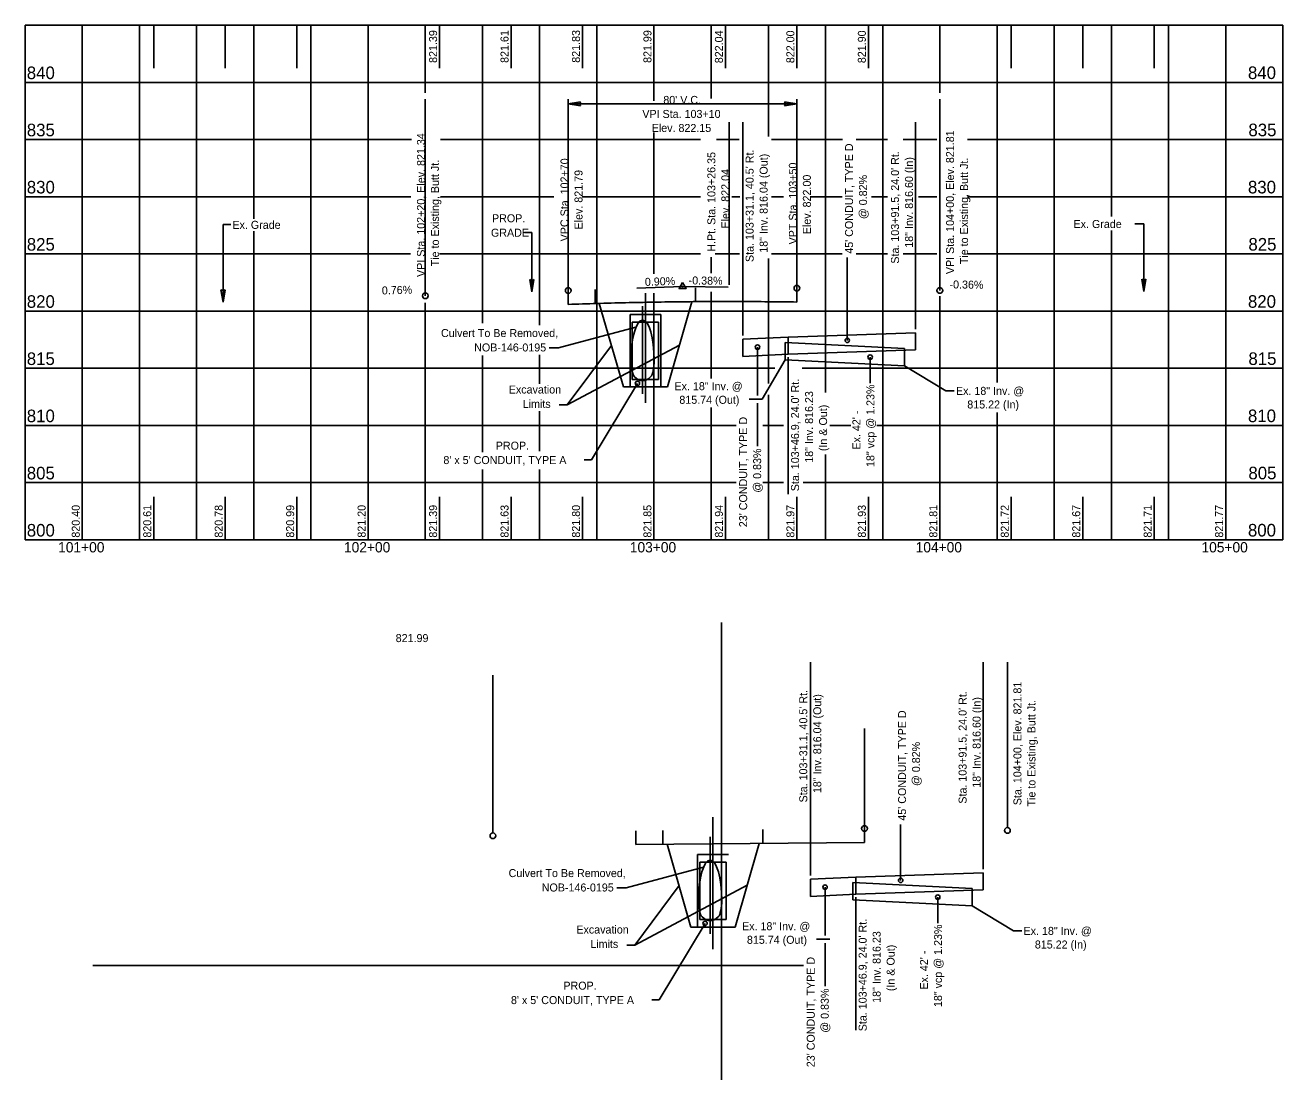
# Model space of a CAD drawing. Extents: x 1055 to 1496, y 611 to 1175.
# Drawn here: x 1055 to 1495, y 611.1 to 980 of the extents above; entities that cross this region are included whole.
import ezdxf

# ---------------------------------------------------------------- set-up
doc = ezdxf.new("R2010")
doc.units = 0
for name, color, linetype in [('BR_P_Gen_Joint_Filler', 7, 'Continuous'), ('Default', 7, 'Continuous'), ('DR_P_Culvert', 7, 'Continuous'), ('DR_X_Culvert', 7, 'Continuous'), ('PF_P_Grade_Line', 7, 'Continuous'), ('PF_P_Text', 7, 'Continuous'), ('PF_P_Text_Strip_Grades_20', 7, 'Continuous'), ('PF_X_Text', 7, 'Continuous'), ('SH_Major_Grid_Line', 7, 'Continuous')]:
    doc.layers.add(name, color=color, linetype=linetype)

msp = doc.modelspace()

# ---------------------------------------------------------------- linework, layer by layer
at = {"layer": 'BR_P_Gen_Joint_Filler'}
for p, q in [((1245, 952.47), (1249.33, 953.19)), ((1249.31, 951.75), (1245, 952.47)), ((1249.31, 951.75), (1249.31, 951.75)), ((1249.33, 953.19), (1249.33, 953.19)), ((1325, 952.47), (1320.67, 951.75)), ((1320.67, 951.75), (1320.67, 951.75)), ((1320.69, 953.19), (1320.69, 953.19)), ((1320.69, 953.19), (1325, 952.47)), ((1232.25, 886.7), (1231.52, 891.03)), ((1231.52, 891.03), (1231.52, 891.03)), ((1232.97, 891.01), (1232.25, 886.7)), ((1232.97, 891.01), (1232.97, 891.01)), ((1446.4, 886.8), (1445.68, 891.13)), ((1445.68, 891.13), (1445.68, 891.13)), ((1447.12, 891.12), (1446.4, 886.8)), ((1447.12, 891.12), (1447.12, 891.12)), ((1124.23, 883.1), (1123.51, 887.43)), ((1123.51, 887.43), (1123.51, 887.43)), ((1124.95, 887.42), (1124.23, 883.1)), ((1124.95, 887.42), (1124.95, 887.42))]:
    msp.add_line(p, q, dxfattribs=at)
for centre, start, end in [((1250.42, 952.46), 146.178, 212.8588), ((1319.58, 952.48), 326.178, 32.8588), ((1232.26, 892.12), 236.178, 302.8588), ((1446.41, 892.22), 236.178, 302.8588), ((1124.24, 888.52), 236.178, 302.8588)]:
    msp.add_arc(centre, 1.31, start, end, dxfattribs=at)
at = {"layer": 'DR_P_Culvert'}
for p, q in [((1272, 847.95), (1272, 886.27)), ((1266.61, 878.79), (1277.38, 878.79)), ((1266.61, 853.45), (1266.61, 878.79)), ((1267.38, 876.12), (1276.62, 876.12)), ((1267.38, 856.12), (1267.38, 876.12)), ((1276.62, 856.12), (1276.62, 876.12)), ((1277.38, 853.45), (1277.38, 878.79)), ((1321.94, 870.92), (1366.47, 872.4)), ((1366.47, 866.4), (1366.47, 872.4)), ((1306.13, 870.16), (1321.94, 870.92)), ((1306.13, 864.16), (1306.13, 870.16)), ((1321.94, 864.92), (1321.94, 870.92)), ((1306.13, 864.16), (1321.94, 864.92)), ((1321.94, 864.92), (1366.47, 866.4)), ((1267.38, 856.12), (1276.62, 856.12)), ((1266.61, 853.45), (1277.38, 853.45)), ((1295.64, 656.83), (1295.64, 702.97)), ((1290.25, 689.91), (1301.03, 689.91)), ((1290.25, 664.58), (1290.25, 689.91)), ((1291.03, 687.25), (1300.26, 687.25)), ((1291.03, 667.25), (1291.03, 687.25)), ((1300.26, 667.25), (1300.26, 687.25)), ((1329.78, 681.29), (1345.59, 682.05)), ((1345.59, 682.05), (1390.12, 683.53)), ((1345.59, 676.05), (1345.59, 682.05)), ((1390.12, 677.53), (1390.12, 683.53)), ((1329.78, 675.29), (1329.78, 681.29)), ((1329.78, 675.29), (1345.59, 676.05)), ((1345.59, 676.05), (1390.12, 677.53)), ((1290.25, 664.58), (1301.03, 664.58)), ((1291.03, 667.25), (1300.26, 667.25))]:
    msp.add_line(p, q, dxfattribs=at)
at = {"layer": 'DR_X_Culvert'}
for p, q in [((1271, 851.04), (1271, 881.66)), ((1320.9, 868.96), (1362.64, 866.88)), ((1320.9, 868.96), (1320.9, 862.96)), ((1362.64, 866.88), (1362.64, 860.88)), ((1320.9, 862.96), (1362.64, 860.88)), ((1294.65, 662.16), (1294.65, 696.08)), ((1344.55, 680.09), (1386.29, 678.01)), ((1344.55, 680.09), (1344.55, 674.09)), ((1386.29, 678.01), (1386.29, 672.01)), ((1344.55, 674.09), (1386.29, 672.01))]:
    msp.add_line(p, q, dxfattribs=at)
for centre, major_axis, ratio, start_param, end_param in [((1271, 862.73), (0, 14.12), 0.288687, 4.717121, 7.849249), ((1268.66, 862.77), (0, -6), 0.288688, 4.707657, 5.99655), ((1273.34, 862.77), (0, -6), 0.288688, 0.286636, 1.575529), ((1271, 890.32), (0, 34.72), 0.288687, 2.854957, 3.428228), ((1294.65, 673.86), (0, 14.12), 0.288687, 4.717121, 7.849249), ((1292.3, 673.9), (0, -6), 0.288688, 4.707657, 5.99655), ((1296.99, 673.9), (0, -6), 0.288688, 0.286636, 1.575529), ((1294.65, 701.45), (0, 34.72), 0.288687, 2.854957, 3.428228)]:
    msp.add_ellipse(centre, major_axis=major_axis, ratio=ratio, start_param=start_param, end_param=end_param, dxfattribs=at)
at = {"layer": 'PF_P_Grade_Line'}
for p, q in [((1245, 882.29), (1245, 887.12)), ((1254.44, 882.64), (1254.44, 887.5)), ((1289.48, 883.3), (1289.48, 888.13)), ((1325, 883.06), (1325, 887.89)), ((1264.29, 853.45), (1255.83, 882.68)), ((1279.69, 853.45), (1288.27, 883.29)), ((1264.29, 853.45), (1266.61, 853.45)), ((1277.38, 853.45), (1279.69, 853.45)), ((1268.65, 693.41), (1268.65, 698.25)), ((1278.09, 693.5), (1278.09, 698.34)), ((1313.13, 693.84), (1313.13, 698.67)), ((1348.65, 694.18), (1348.65, 699.01)), ((1268.65, 693.41), (1348.65, 694.18)), ((1287.94, 664.58), (1279.56, 693.52)), ((1303.34, 664.58), (1311.75, 693.83)), ((1287.94, 664.58), (1290.25, 664.58)), ((1301.03, 664.58), (1303.34, 664.58))]:
    msp.add_line(p, q, dxfattribs=at)
msp.add_open_spline([(1245, 882.33), (1285, 883.77), (1325, 883.16)], degree=2, dxfattribs=at)
at = {"layer": 'PF_P_Text'}
for p, q in [((1195, 885.36), (1195, 954.06)), ((1245, 887.16), (1245, 954.06)), ((1325, 888), (1325, 954.06)), ((1375, 887.24), (1375, 954.06)), ((1301.35, 889.18), (1301.35, 946.09)), ((1306.13, 871.47), (1306.13, 946.09)), ((1366.47, 873.65), (1366.47, 946.09)), ((1285, 888.6), (1269.01, 888.02)), ((1285, 888.6), (1285, 888.6)), ((1285, 888.6), (1301, 888.36)), ((1321.94, 815.94), (1321.94, 863.93)), ((1329.78, 682.6), (1329.78, 757.22)), ((1390.12, 684.78), (1390.12, 757.22)), ((1398.65, 699.36), (1398.65, 757.22)), ((1218.65, 697.49), (1218.65, 752.66)), ((1348.65, 699.01), (1348.65, 734.01)), ((1345.59, 628.46), (1345.59, 675.05))]:
    msp.add_line(p, q, dxfattribs=at)
msp.add_lwpolyline([(1285, 890.04), (1283.75, 887.88), (1286.25, 887.88)], close=True, dxfattribs=at)
for centre, radius in [((1325, 888), 1), ((1195, 885.36), 1), ((1245, 887.16), 1), ((1285, 888.6), 0.1), ((1285, 888.6), 0.1), ((1375, 887.24), 1), ((1348.65, 699.01), 1), ((1218.65, 696.49), 1), ((1398.65, 698.36), 1)]:
    msp.add_circle(centre, radius, dxfattribs=at)
at = {"layer": 'PF_X_Text'}
for p, q in [((1245, 952.47), (1325, 952.47)), ((1124.23, 910.24), (1126.98, 910.24)), ((1124.23, 883.1), (1124.23, 910.24)), ((1229.68, 907.44), (1232.25, 907.44)), ((1232.25, 886.7), (1232.25, 907.44)), ((1443.16, 910.56), (1446.4, 910.56)), ((1446.4, 886.8), (1446.4, 910.56)), ((1342.61, 869.76), (1342.61, 898.72)), ((1241.59, 867.19), (1268.69, 874.36)), ((1238.36, 867.19), (1241.59, 867.19)), ((1244.64, 847.16), (1283.9, 868.08)), ((1244.64, 847.16), (1260.1, 867.92)), ((1311.2, 850.5), (1311.2, 867.39)), ((1312.83, 849.15), (1320.9, 862.96)), ((1350.63, 854.78), (1350.63, 863.9)), ((1377.07, 852.15), (1362.64, 860.88)), ((1253.18, 828), (1269.21, 854.71)), ((1377.07, 852.15), (1380.07, 852.15)), ((1241.84, 847.16), (1244.64, 847.16)), ((1308.25, 849.15), (1312.83, 849.15)), ((1311.2, 832.8), (1311.2, 847.79)), ((1250.54, 828), (1253.18, 828)), ((1361.29, 680.89), (1361.29, 700.42)), ((1265.24, 678.31), (1292.33, 685.49)), ((1262.01, 678.31), (1265.24, 678.31)), ((1268.28, 658.28), (1307.55, 679.2)), ((1268.28, 658.28), (1283.75, 679.05)), ((1334.85, 661.63), (1334.85, 678.51)), ((1374.28, 665.91), (1374.28, 675.03)), ((1400.72, 663.27), (1386.29, 672.01)), ((1276.82, 639.12), (1292.86, 665.83)), ((1331.89, 660.27), (1336.48, 660.27)), ((1400.72, 663.27), (1403.72, 663.27)), ((1265.49, 658.28), (1268.28, 658.28)), ((1334.85, 643.93), (1334.85, 658.92)), ((1274.19, 639.12), (1276.82, 639.12))]:
    msp.add_line(p, q, dxfattribs=at)
for centre in [(1311.2, 867.39), (1342.61, 869.76), (1350.63, 863.9), (1269.21, 854.71), (1334.85, 678.51), (1361.29, 680.89), (1374.28, 675.03), (1292.86, 665.83)]:
    msp.add_circle(centre, 0.775, dxfattribs=at)
at = {"layer": 'SH_Major_Grid_Line'}
for p, q in [((1055, 800), (1055, 980)), ((1055, 980), (1495, 980)), ((1075, 800), (1075, 980)), ((1095, 800), (1095, 980)), ((1100, 965), (1100, 980)), ((1115, 800), (1115, 980)), ((1125, 965), (1125, 980)), ((1135, 912.29), (1135, 980)), ((1150, 965), (1150, 980)), ((1155, 800), (1155, 980)), ((1175, 800), (1175, 980)), ((1195, 956.28), (1195, 980)), ((1200, 965), (1200, 980)), ((1215, 875.8), (1215, 980)), ((1225, 965), (1225, 980)), ((1235, 875.07), (1235, 980)), ((1250, 965), (1250, 980)), ((1255, 800), (1255, 980)), ((1275, 953.53), (1275, 980)), ((1295, 954.3), (1295, 980)), ((1300, 965), (1300, 980)), ((1315, 941.05), (1315, 980)), ((1325, 965), (1325, 980)), ((1335, 851.47), (1335, 980)), ((1350, 965), (1350, 980)), ((1355, 800), (1355, 980)), ((1375, 956.28), (1375, 980)), ((1395, 855), (1395, 980)), ((1400, 965), (1400, 980)), ((1415, 800), (1415, 980)), ((1425, 965), (1425, 980)), ((1435, 913.03), (1435, 980)), ((1450, 965), (1450, 980)), ((1455, 800), (1455, 980)), ((1475, 800), (1475, 980)), ((1495, 800), (1495, 980)), ((1055, 960), (1495, 960)), ((1275, 893.03), (1275, 942.51)), ((1055, 940), (1190.12, 940)), ((1200.25, 940), (1291.26, 940)), ((1296.87, 940), (1304.85, 940)), ((1316.1, 940), (1341, 940)), ((1345.78, 940), (1356.7, 940)), ((1362.18, 940), (1373.96, 940)), ((1384.66, 940), (1495, 940)), ((1055, 920), (1189.95, 920)), ((1200.25, 920), (1240, 920)), ((1249.86, 920), (1291.26, 920)), ((1302.25, 920), (1305.01, 920)), ((1316.1, 920), (1320.29, 920)), ((1329.89, 920), (1340.82, 920)), ((1351.06, 920), (1356.7, 920)), ((1367.5, 920), (1373.96, 920)), ((1384.66, 920), (1495, 920)), ((1135, 800), (1135, 907.91)), ((1435, 800), (1435, 908.17)), ((1055, 900), (1189.81, 900)), ((1200.01, 900), (1291.26, 900)), ((1295, 893.21), (1295, 898.89)), ((1296.39, 900), (1304.93, 900)), ((1315, 854.72), (1315, 898.41)), ((1316.1, 900), (1340.82, 900)), ((1345.78, 900), (1356.7, 900)), ((1362.18, 900), (1373.96, 900)), ((1384.66, 900), (1495, 900)), ((1275, 800), (1275, 886.27)), ((1295, 856.4), (1295, 886.69)), ((1375, 800), (1375, 885.25)), ((1195, 800), (1195, 882.91)), ((1055, 880), (1495, 880)), ((1215, 830.66), (1215, 864.48)), ((1235, 854.51), (1235, 864.66)), ((1055, 860), (1317.31, 860)), ((1326.85, 860), (1495, 860)), ((1315, 800), (1315, 850.76)), ((1235, 830.95), (1235, 844.98)), ((1295, 800), (1295, 846.24)), ((1395, 800), (1395, 844.49)), ((1055, 840), (1303.71, 840)), ((1313.02, 840), (1320.36, 840)), ((1336.47, 840), (1343.84, 840)), ((1352.97, 840), (1495, 840)), ((1335, 800), (1335, 829.79)), ((1215, 800), (1215, 824.56)), ((1235, 800), (1235, 824.56)), ((1055, 820), (1303.78, 820)), ((1313.02, 820), (1320.34, 820)), ((1327.13, 820), (1495, 820)), ((1100, 800), (1100, 815)), ((1125, 800), (1125, 815)), ((1125, 800), (1125, 815)), ((1150, 800), (1150, 815)), ((1200, 800), (1200, 815)), ((1225, 800), (1225, 815)), ((1225, 800), (1225, 815)), ((1250, 800), (1250, 815)), ((1300, 800), (1300, 815)), ((1325, 800), (1325, 815)), ((1350, 800), (1350, 815)), ((1400, 800), (1400, 815)), ((1425, 800), (1425, 815)), ((1450, 800), (1450, 815)), ((1055, 800), (1495, 800)), ((1298.65, 611.13), (1298.65, 771.13)), ((1078.65, 651.13), (1327.36, 651.13))]:
    msp.add_line(p, q, dxfattribs=at)

# ---------------------------------------------------------------- texts
at = {"layer": 'Default'}
for s, height, p in [('840', 4.4, (1055.57, 961.14)), ('840', 4.4, (1482.79, 961.16)), ('835', 4.4, (1055.57, 941.14)), ('835', 4.4, (1482.95, 941.16)), ('830', 4.4, (1055.57, 921.14)), ('830', 4.4, (1482.79, 921.16)), ('825', 4.4, (1055.57, 901.14)), ('825', 4.4, (1482.95, 901.16)), ('820', 4.4, (1055.57, 881.14)), ('820', 4.4, (1482.79, 881.16)), ('815', 4.4, (1055.57, 861.14)), ('815', 4.4, (1482.95, 861.16)), ('810', 4.4, (1055.57, 841.14)), ('810', 4.4, (1482.79, 841.16)), ('805', 4.4, (1055.57, 821.14)), ('805', 4.4, (1482.95, 821.16)), ('800', 4.4, (1055.57, 801.14)), ('800', 4.4, (1482.79, 801.16)), ('101+00', 3.6, (1066.54, 795.6)), ('102+00', 3.6, (1166.54, 795.6)), ('103+00', 3.6, (1266.54, 795.6)), ('104+00', 3.6, (1366.54, 795.6)), ('105+00', 3.6, (1466.54, 795.6))]:
    msp.add_text(s, height=height, dxfattribs=at).set_placement(p)
at = {"layer": 'PF_P_Text'}
for s, p in [("80' V.C.", (1278.26, 952.45)), ('VPI Sta. 103+10', (1270.92, 947.55)), ('Elev. 822.15', (1274.2, 942.65)), ('PROP.', (1218.33, 911.05)), ('GRADE', (1217.96, 906.01)), ('Culvert To Be Removed,', (1200.48, 870.92)), ('NOB-146-0195', (1212.09, 865.88)), ('Excavation', (1224.19, 851.17)), ('Limits', (1229.07, 846.13)), ('PROP.', (1219.65, 831.53)), ("8' x 5' CONDUIT, TYPE A", (1201.32, 826.49)), ('821.99', (1184.63, 764.23)), ('Culvert To Be Removed,', (1224.13, 682.04)), ('NOB-146-0195', (1235.73, 677)), ('Excavation', (1247.84, 662.29)), ('Limits', (1252.72, 657.25)), ('PROP.', (1243.3, 642.66)), ("8' x 5' CONDUIT, TYPE A", (1224.96, 637.62))]:
    msp.add_text(s, height=2.8, dxfattribs=at).set_placement(p)
for s, rotation, p in [('VPI Sta. 102+20, Elev. 821.34', 90, (1194.87, 891.93)), ('VPI Sta. 104+00, Elev. 821.81', 90, (1379.97, 892.93)), ("45' CONDUIT, TYPE D", 90, (1344.63, 900.06)), ('VPC Sta. 102+70', 90, (1245.09, 904.38)), ('H.Pt. Sta. 103+26.35', 90, (1296.47, 900.77)), ("Sta. 103+31.1, 40.5' Rt.", 90, (1309.85, 897.15)), ('18" Inv. 816.04 (Out)', 90, (1314.75, 900.39)), ("Sta. 103+91.5, 24.0' Rt.", 90, (1360.71, 896.58)), ('18" Inv. 816.60 (In)', 90, (1365.61, 902.15)), ('Tie to Existing, Butt Jt.', 90, (1384.87, 896.4)), ('Tie to Existing, Butt Jt.', 90, (1199.77, 895.66)), ('Elev. 821.79', 90, (1249.99, 908.54)), ('Elev. 822.04', 90, (1301.37, 908.87)), ('VPT Sta. 103+50', 90, (1324.98, 903.31)), ('Elev. 822.00', 90, (1329.88, 906.89)), ('@ 0.82%', 90, (1349.53, 912.16)), ('0.76%', 1.6387, (1179.82, 885.8)), ('0.90%', 2.0618, (1271.85, 888.79)), ('-0.38%', 359.1343, (1287.11, 889.35)), ('-0.36%', 359.2188, (1378.37, 887.94)), ("Sta. 103+46.9, 24.0' Rt.", 90, (1325.75, 816.99)), ('18" Inv. 816.23', 90, (1330.65, 826.94)), ('(In & Out)', 90, (1335.55, 831.02)), ("23' CONDUIT, TYPE D", 90, (1307.59, 804.42)), ('@ 0.83%', 90, (1312.49, 816.47)), ('Sta. 104+00, Elev. 821.81', 90, (1403.55, 707.19)), ("Sta. 103+31.1, 40.5' Rt.", 90, (1328.62, 708.15)), ('18" Inv. 816.04 (Out)', 90, (1333.52, 711.4)), ("Sta. 103+91.5, 24.0' Rt.", 90, (1384.36, 707.71)), ('18" Inv. 816.60 (In)', 90, (1389.26, 713.28)), ('Tie to Existing, Butt Jt.', 90, (1408.45, 706.73)), ("45' CONDUIT, TYPE D", 90, (1363.18, 701.77)), ('@ 0.82%', 90, (1368.08, 713.87)), ("Sta. 103+46.9, 24.0' Rt.", 90, (1349.39, 628.11)), ('18" Inv. 816.23', 90, (1354.29, 638.06)), ('(In & Out)', 90, (1359.19, 642.15)), ("23' CONDUIT, TYPE D", 90, (1331.24, 615.54)), ('@ 0.83%', 90, (1336.14, 627.6))]:
    msp.add_text(s, height=2.8, rotation=rotation, dxfattribs=at).set_placement(p)
at = {"layer": 'PF_P_Text_Strip_Grades_20'}
for s, p in [('821.39', (1199.11, 966.79)), ('821.61', (1224.11, 966.8)), ('821.83', (1249.11, 966.85)), ('821.99', (1274.11, 966.79)), ('822.04', (1299.11, 966.69)), ('822.00', (1324.11, 966.71)), ('821.90', (1349.11, 966.71))]:
    msp.add_text(s, height=2.8, rotation=90, dxfattribs=at).set_placement(p)
at = {"layer": 'PF_X_Text'}
for s, p in [('Ex. Grade', (1127.51, 908.76)), ('Ex. Grade', (1421.77, 909.06)), ('Ex. 18" Inv. @', (1282.16, 852.33)), ('Ex. 18" Inv. @', (1380.64, 850.69)), ('815.74 (Out)', (1283.87, 847.57)), ('815.22 (In)', (1384.6, 845.93)), ('Ex. 18" Inv. @', (1305.8, 663.46)), ('Ex. 18" Inv. @', (1404.29, 661.82)), ('815.74 (Out)', (1307.51, 658.7)), ('815.22 (In)', (1408.24, 657.06))]:
    msp.add_text(s, height=2.8, dxfattribs=at).set_placement(p)
for s, p in [('18" vcp @ 1.23%', (1352.11, 825.46)), ("Ex. 42' -", (1347.21, 831.56)), ('820.40', (1074.11, 800.76)), ('820.61', (1099.11, 800.76)), ('820.78', (1124.11, 800.76)), ('820.99', (1149.11, 800.76)), ('821.20', (1174.11, 800.76)), ('821.39', (1199.11, 800.76)), ('821.63', (1224.11, 800.76)), ('821.80', (1249.11, 800.76)), ('821.85', (1274.11, 800.76)), ('821.94', (1299.11, 800.76)), ('821.97', (1324.11, 800.76)), ('821.93', (1349.11, 800.76)), ('821.81', (1374.11, 800.76)), ('821.72', (1399.11, 800.76)), ('821.67', (1424.11, 800.76)), ('821.71', (1449.11, 800.76)), ('821.77', (1474.11, 800.76)), ('18" vcp @ 1.23%', (1375.76, 636.58)), ("Ex. 42' -", (1370.86, 642.68))]:
    msp.add_text(s, height=2.8, rotation=90, dxfattribs=at).set_placement(p)

doc.saveas('drawing.dxf')
